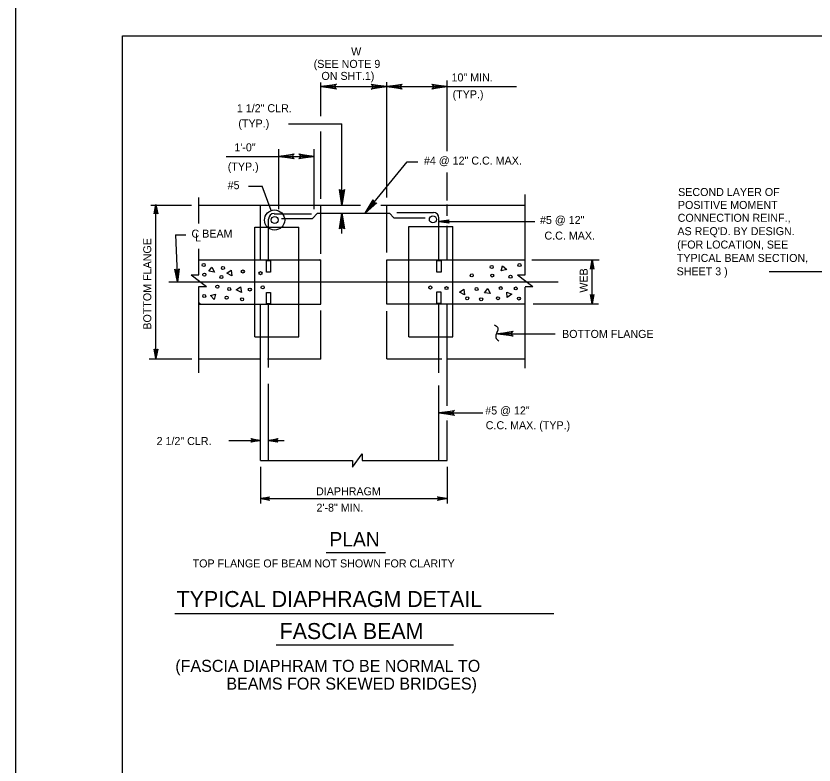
# Model space of a CAD drawing. Extents: x 639980 to 641204, y 298038 to 300414.
# Drawn here: x 639980.3 to 640279.6, y 299531.3 to 299812.3 of the extents above; entities that cross this region are included whole.
import ezdxf

# ---------------------------------------------------------------- set-up
doc = ezdxf.new("R2010")
doc.units = 0
for name, color, linetype in [('2', 7, 'Continuous'), ('3', 7, 'Continuous'), ('PLT-BNDY', 7, 'Continuous')]:
    doc.layers.add(name, color=color, linetype=linetype)

msp = doc.modelspace()

# ---------------------------------------------------------------- linework, layer by layer
at = {"layer": '2'}
for p, q in [((640020.31, 299240.78), (640020.31, 299804.78)), ((640020.31, 299804.78), (640806.31, 299804.78)), ((640142.04, 299761.53), (640142.04, 299788.07)), ((640094.66, 299774.72), (640094.66, 299787.32)), ((640094.66, 299785.77), (640094.66, 299785.77)), ((640094.66, 299785.77), (640119.35, 299785.77)), ((640109.44, 299785.77), (640109.44, 299785.77)), ((640119.35, 299744.16), (640119.35, 299787.43)), ((640119.35, 299785.77), (640142.04, 299785.77)), ((640119.35, 299785.77), (640119.35, 299785.77)), ((640142.04, 299785.77), (640168.01, 299785.77)), ((640082.53, 299771.86), (640102.51, 299771.86)), ((640102.51, 299741.38), (640102.51, 299771.86)), ((640094.66, 299743.75), (640094.66, 299769)), ((640078.85, 299739.88), (640078.85, 299762.36)), ((640092.16, 299739.88), (640092.16, 299762.36)), ((640059.1, 299759.62), (640078.85, 299759.62)), ((640078.85, 299759.62), (640092.16, 299759.62)), ((640111.27, 299738.26), (640127.05, 299757.63)), ((640127.05, 299757.63), (640130.99, 299757.63)), ((640142.04, 299743.01), (640142.04, 299753.52)), ((640067.48, 299748.48), (640072.6, 299748.48)), ((640075.98, 299739.28), (640072.6, 299748.48)), ((640048.93, 299734.45), (640048.93, 299744.14)), ((640171.3, 299715.13), (640171.3, 299745.26)), ((640030.87, 299741.38), (640046.18, 299741.38)), ((640032.79, 299683.76), (640032.79, 299741.51)), ((640048.93, 299741.38), (640071.97, 299741.38)), ((640071.97, 299720.76), (640071.97, 299741.38)), ((640071.97, 299741.38), (640109.47, 299741.38)), ((640094.66, 299723.06), (640094.66, 299741.26)), ((640117.14, 299741.38), (640142.04, 299741.38)), ((640119.35, 299723.51), (640119.35, 299741.38)), ((640142.04, 299737.33), (640142.04, 299741.63)), ((640142.04, 299741.38), (640171.3, 299741.38)), ((640077.1, 299738.13), (640091.09, 299738.13)), ((640091.49, 299736.33), (640093.41, 299738.26)), ((640093.41, 299738.26), (640120.35, 299738.26)), ((640102.51, 299730.68), (640102.51, 299738.26)), ((640122.03, 299736.58), (640120.35, 299738.26)), ((640123.12, 299738.51), (640136.91, 299738.51)), ((640074.97, 299720.76), (640074.97, 299736.13)), ((640079.82, 299736.33), (640091.49, 299736.33)), ((640122.03, 299736.58), (640133.72, 299736.58)), ((640138.91, 299721.01), (640138.91, 299736.51)), ((640138.91, 299735.21), (640174.84, 299735.21)), ((640069.91, 299691.88), (640069.91, 299733.13)), ((640069.91, 299733.13), (640086.41, 299733.13)), ((640086.41, 299691.88), (640086.41, 299733.13)), ((640127.6, 299733.38), (640144.1, 299733.38)), ((640127.6, 299691.88), (640127.6, 299733.38)), ((640142.04, 299721.01), (640142.04, 299733.61)), ((640144.1, 299691.88), (640144.1, 299733.38)), ((640040.09, 299730.19), (640040.93, 299712.51)), ((640040.09, 299730.19), (640043.95, 299730.19)), ((640048.93, 299715.13), (640048.93, 299724.97)), ((640048.93, 299720.76), (640071.97, 299720.76)), ((640071.97, 299720.76), (640094.66, 299720.76)), ((640094.66, 299704.13), (640094.66, 299720.88)), ((640119.35, 299704.13), (640119.35, 299720.76)), ((640119.35, 299720.76), (640142.04, 299720.76)), ((640142.04, 299720.76), (640171.3, 299720.76)), ((640173.8, 299720.76), (640199.05, 299720.76)), ((640196.43, 299704.26), (640196.43, 299720.76)), ((640262.77, 299716.48), (640289.71, 299716.48)), ((640046.05, 299715.13), (640048.93, 299715.13)), ((640046.05, 299715.13), (640051.8, 299710.76)), ((640168.43, 299715.13), (640171.3, 299715.13)), ((640168.43, 299715.13), (640174.18, 299710.76)), ((640037.68, 299712.51), (640183.68, 299712.51)), ((640048.93, 299678.38), (640048.93, 299710.76)), ((640048.93, 299710.76), (640051.8, 299710.76)), ((640106.94, 299712.51), (640106.94, 299712.51)), ((640171.3, 299710.76), (640174.18, 299710.76)), ((640171.3, 299680.13), (640171.3, 299710.51)), ((640119.35, 299704.26), (640142.04, 299704.26)), ((640138.91, 299678.38), (640138.91, 299704.26)), ((640142.04, 299704.26), (640171.3, 299704.26)), ((640142.04, 299666.02), (640142.04, 299704.26)), ((640174.3, 299704.26), (640198.8, 299704.26)), ((640048.93, 299704.13), (640071.97, 299704.13)), ((640071.97, 299645.51), (640071.97, 299704.13)), ((640071.97, 299704.13), (640094.66, 299704.13)), ((640074.97, 299680.41), (640074.97, 299704.13)), ((640094.66, 299683.51), (640094.66, 299701.84)), ((640119.35, 299683.63), (640119.35, 299701.62)), ((640160.89, 299693.09), (640182.49, 299693.09)), ((640069.91, 299691.88), (640086.41, 299691.88)), ((640127.6, 299691.88), (640144.1, 299691.88)), ((640030.2, 299683.63), (640046.3, 299683.63)), ((640048.93, 299683.63), (640071.97, 299683.63)), ((640074.63, 299683.63), (640094.66, 299683.63)), ((640119.35, 299683.63), (640140.04, 299683.63)), ((640142.04, 299683.63), (640171.3, 299683.63)), ((640074.97, 299645.51), (640074.97, 299674.26)), ((640138.91, 299645.51), (640138.91, 299673.63)), ((640138.91, 299663.38), (640155.41, 299663.38)), ((640142.04, 299645.51), (640142.04, 299660.6)), ((640060.1, 299653.01), (640071.97, 299653.01)), ((640074.97, 299653.01), (640080.86, 299653.01)), ((640106.44, 299643.01), (640110.07, 299648.01)), ((640110.07, 299648.01), (640110.07, 299645.51)), ((640071.97, 299645.51), (640086.79, 299645.51)), ((640081.69, 299645.51), (640106.44, 299645.51)), ((640106.44, 299645.51), (640106.44, 299643.01)), ((640110.07, 299645.51), (640133.19, 299645.51)), ((640133.41, 299645.51), (640142.04, 299645.51)), ((640071.97, 299643.13), (640071.97, 299629.38)), ((640142.04, 299643.13), (640142.04, 299629.38)), ((640071.97, 299631.26), (640142.04, 299631.26)), ((640096.67, 299611.07), (640118.83, 299611.07)), ((640039.91, 299588.23), (640182.04, 299588.23)), ((640077.91, 299576.48), (640144.41, 299576.48))]:
    msp.add_line(p, q, dxfattribs=at)
for points in [[(640100.2, 299785.07), (640099.99, 299785.47), (640094.66, 299785.77), (640100.2, 299785.07), (640100.48, 299784.83), (640094.66, 299785.77), (640099.99, 299786.03), (640100.18, 299786.43), (640094.66, 299785.77), (640100.48, 299786.69), (640100.18, 299786.43)], [(640113.81, 299786.46), (640114.02, 299786.06), (640119.35, 299785.77), (640113.81, 299786.46), (640113.53, 299786.7), (640119.35, 299785.77), (640114.03, 299785.5), (640113.83, 299785.11), (640119.35, 299785.77), (640113.53, 299784.84), (640113.83, 299785.11)], [(640124.89, 299785.07), (640124.68, 299785.47), (640119.35, 299785.77), (640124.89, 299785.07), (640125.17, 299784.83), (640119.35, 299785.77), (640124.68, 299786.03), (640124.87, 299786.43), (640119.35, 299785.77), (640125.17, 299786.69), (640124.87, 299786.43)], [(640136.5, 299786.46), (640136.71, 299786.06), (640142.04, 299785.77), (640136.5, 299786.46), (640136.22, 299786.7), (640142.04, 299785.77), (640136.71, 299785.5), (640136.52, 299785.11), (640142.04, 299785.77), (640136.22, 299784.84), (640136.52, 299785.11)], [(640084.39, 299758.92), (640084.18, 299759.33), (640078.85, 299759.62), (640084.39, 299758.92), (640084.67, 299758.68), (640078.85, 299759.62), (640084.18, 299759.88), (640084.37, 299760.28), (640078.85, 299759.62), (640084.67, 299760.54), (640084.37, 299760.28)], [(640086.63, 299760.31), (640086.83, 299759.91), (640092.16, 299759.62), (640086.63, 299760.31), (640086.34, 299760.56), (640092.16, 299759.62), (640086.84, 299759.36), (640086.64, 299758.96), (640092.16, 299759.62), (640086.34, 299758.7), (640086.64, 299758.96)], [(640103.21, 299746.92), (640102.81, 299746.71), (640102.51, 299741.38), (640103.21, 299746.92), (640103.45, 299747.2), (640102.51, 299741.38), (640102.25, 299746.71), (640101.85, 299746.9), (640102.51, 299741.38), (640101.59, 299747.2), (640101.85, 299746.9)], [(640115.3, 299742.11), (640114.86, 299742.2), (640111.27, 299738.26), (640115.3, 299742.11), (640115.67, 299742.18), (640111.27, 299738.26), (640114.43, 299742.55), (640114.24, 299742.95), (640111.27, 299738.26), (640114.23, 299743.35), (640114.24, 299742.95)], [(640032.29, 299738.26), (640032.66, 299738.38), (640032.79, 299741.51), (640032.29, 299738.26), (640032.16, 299738.13), (640032.79, 299741.51), (640033.04, 299738.38), (640033.29, 299738.26), (640032.79, 299741.51), (640033.54, 299738.13), (640033.29, 299738.26)], [(640101.82, 299732.72), (640102.22, 299732.93), (640102.51, 299738.26), (640101.82, 299732.72), (640101.57, 299732.44), (640102.51, 299738.26), (640102.78, 299732.93), (640103.17, 299732.74), (640102.51, 299738.26), (640103.44, 299732.44), (640103.17, 299732.74)], [(640142.6, 299734.75), (640142.47, 299735.02), (640138.91, 299735.21), (640142.6, 299734.75), (640142.79, 299734.59), (640138.91, 299735.21), (640142.46, 299735.39), (640142.59, 299735.65), (640138.91, 299735.21), (640142.79, 299735.83), (640142.59, 299735.65)], [(640094.66, 299720.26), (640094.04, 299720.76)], [(640195.93, 299717.51), (640196.18, 299717.63), (640196.43, 299720.76), (640195.93, 299717.51), (640195.8, 299717.26), (640196.43, 299720.76), (640196.55, 299717.63), (640196.93, 299717.51), (640196.43, 299720.76), (640197.05, 299717.26), (640196.93, 299717.51)], [(640041.29, 299717.14), (640040.96, 299716.95), (640040.93, 299712.51), (640041.29, 299717.14), (640041.48, 299717.39), (640040.93, 299712.51), (640040.5, 299716.93), (640040.16, 299717.08), (640040.93, 299712.51), (640039.93, 299717.31), (640040.16, 299717.08)], [(640196.93, 299707.51), (640196.68, 299707.51), (640196.43, 299704.26), (640196.93, 299707.51), (640197.05, 299707.76), (640196.43, 299704.26), (640196.18, 299707.38), (640195.93, 299707.51), (640196.43, 299704.26), (640195.8, 299707.76), (640195.93, 299707.51)], [(640049.43, 299704.26), (640048.93, 299704.76)], [(640166.42, 299692.4), (640166.22, 299692.8), (640160.89, 299693.09), (640166.42, 299692.4), (640166.71, 299692.15), (640160.89, 299693.09), (640166.21, 299693.35), (640166.41, 299693.75), (640160.89, 299693.09), (640166.71, 299694.02), (640166.41, 299693.75)], [(640033.29, 299687.13), (640033.04, 299687.01), (640032.79, 299683.76), (640033.29, 299687.13), (640033.54, 299687.26), (640032.79, 299683.76), (640032.66, 299687.01), (640032.41, 299687.13), (640032.79, 299683.76), (640032.16, 299687.26), (640032.41, 299687.13)], [(640144.45, 299662.69), (640144.24, 299663.09), (640138.91, 299663.38), (640144.45, 299662.69), (640144.73, 299662.44), (640138.91, 299663.38), (640144.24, 299663.64), (640144.43, 299664.04), (640138.91, 299663.38), (640144.73, 299664.31), (640144.43, 299664.04)], [(640142.04, 299661.38), (640142.04, 299661.38)], [(640068.6, 299653.51), (640068.72, 299653.26), (640071.97, 299653.01), (640068.6, 299653.51), (640068.47, 299653.76), (640071.97, 299653.01), (640068.72, 299652.88), (640068.6, 299652.63), (640071.97, 299653.01), (640068.47, 299652.38), (640068.6, 299652.63)], [(640078.35, 299652.51), (640078.22, 299652.88), (640074.97, 299653.01), (640078.35, 299652.51), (640078.47, 299652.38), (640074.97, 299653.01), (640078.22, 299653.26), (640078.35, 299653.51), (640074.97, 299653.01), (640078.47, 299653.76), (640078.35, 299653.51)], [(640142.04, 299654.13), (640142.04, 299654.13)], [(640142.04, 299646.76), (640142.04, 299646.76)], [(640075.1, 299630.76), (640074.97, 299631.01), (640071.85, 299631.26), (640075.1, 299630.76), (640075.35, 299630.51), (640071.85, 299631.26), (640074.97, 299631.38), (640075.1, 299631.63), (640071.85, 299631.26), (640075.35, 299631.88), (640075.1, 299631.63)], [(640138.66, 299631.76), (640138.79, 299631.38), (640141.91, 299631.26), (640138.66, 299631.76), (640138.41, 299631.88), (640141.91, 299631.26), (640138.79, 299631.01), (640138.66, 299630.76), (640141.91, 299631.26), (640138.41, 299630.51), (640138.66, 299630.76)]]:
    msp.add_lwpolyline(points, dxfattribs=at)
for points in [[(640074.22, 299720.55), (640075.78, 299720.55), (640075.78, 299716.22), (640074.22, 299716.22)], [(640138.14, 299720.57), (640139.7, 299720.57), (640139.7, 299716.24), (640138.14, 299716.24)], [(640052.59, 299716.54), (640053.74, 299718.08), (640054.71, 299716.25)], [(640059.34, 299715.84), (640060.95, 299716.89), (640061.24, 299714.84)], [(640162.24, 299716.73), (640162.8, 299718.58), (640164.33, 299717.19)], [(640062.93, 299709.62), (640064.55, 299710.67), (640064.83, 299708.62)], [(640053.25, 299707.5), (640055.12, 299707.93), (640054.69, 299705.91)], [(640074.2, 299708.59), (640075.76, 299708.59), (640075.76, 299704.26), (640074.2, 299704.26)], [(640138.07, 299708.82), (640139.63, 299708.82), (640139.63, 299704.48), (640138.07, 299704.48)], [(640146.61, 299708.72), (640148.23, 299709.77), (640148.51, 299707.72)], [(640156.05, 299708.49), (640157.2, 299710.02), (640158.17, 299708.2)], [(640164.44, 299706.74), (640164.34, 299708.66), (640166.25, 299707.88)]]:
    msp.add_lwpolyline(points, close=True, dxfattribs=at)
for centre, radius in [((640077.29, 299735.74), 3.78), ((640136.65, 299735.98), 1.32), ((640077.34, 299735.75), 1.32), ((640050.72, 299718.88), 0.571), ((640169.13, 299718.88), 0.571), ((640057.94, 299717.75), 0.571), ((640065.38, 299716.44), 0.571), ((640072.01, 299715.81), 0.571), ((640158.71, 299718.11), 0.571), ((640050.95, 299715.27), 0.571), ((640057.35, 299714.37), 0.571), ((640151.22, 299715), 0.571), ((640158.89, 299714.91), 0.571), ((640165.75, 299714.5), 0.571), ((640055.82, 299710.76), 0.571), ((640060.28, 299709.86), 0.571), ((640068, 299709.67), 0.571), ((640072.82, 299710.49), 0.571), ((640135.71, 299710.44), 0.571), ((640141.75, 299710.22), 0.571), ((640153.03, 299709.86), 0.571), ((640162.09, 299710.22), 0.571), ((640167.73, 299710.08), 0.571), ((640050.9, 299707.24), 0.571), ((640059.29, 299706.61), 0.571), ((640065.11, 299706.02), 0.571), ((640149.51, 299706.38), 0.571), ((640154.74, 299706.02), 0.571), ((640161.06, 299706.43), 0.571), ((640168.9, 299706.29), 0.571)]:
    msp.add_circle(centre, radius, dxfattribs=at)
for centre, start, end in [((640077.09, 299736.11), 90, 180), ((640136.87, 299736.49), 0, 90)]:
    msp.add_arc(centre, 2.06, start, end, dxfattribs=at)
msp.add_spline([(640159.66, 299696.48), (640161.01, 299695.24), (640160.22, 299691.75), (640161.35, 299690.39)], degree=3, dxfattribs=at)
at = {"layer": 'PLT-BNDY'}
msp.add_lwpolyline([(639980.31, 299819.78), (640821.31, 299819.78), (640821.31, 299225.78), (639980.31, 299225.78)], close=True, dxfattribs=at)

# ---------------------------------------------------------------- texts
at = {"layer": '2'}
for s, height, p in [('W', 3, (640106, 299797.47)), ('(SEE NOTE 9', 3, (640091.95, 299792.8)), ('ON SHT.1)', 3, (640094.86, 299788.3)), ('10" MIN.', 3, (640143.63, 299787.72)), ('(TYP.)', 3, (640144.04, 299781.39)), ('1 1/2" CLR.', 3, (640063.13, 299776.19)), ('(TYP.)', 3, (640063.7, 299770.46)), ('1\'-0"', 3, (640062.2, 299761.51)), ('#4 @ 12" C.C. MAX.', 3, (640133.29, 299756.53)), ('(TYP.)', 3, (640059.73, 299754.29)), ('#5', 3, (640059.68, 299747.32)), ('#5 @ 12"', 3, (640176.81, 299734.27)), ('C BEAM', 3, (640046.12, 299729.14)), ('C.C. MAX.', 3, (640178.48, 299728.41)), ('L', 3, (640047.44, 299727.71)), ('BOTTOM FLANGE', 3, (640185.08, 299691.53)), ('#5 @ 12"', 3, (640156.27, 299662.82)), ('C.C. MAX. (TYP.)', 3, (640156.47, 299657.29)), ('2 1/2" CLR.', 3, (640033.04, 299651.36)), ('DIAPHRAGM', 3, (640092.82, 299632.51)), ('2\'-8" MIN.', 3, (640092.99, 299626.38)), ('PLAN', 5.4, (640097.85, 299613.31)), ('TOP FLANGE OF BEAM NOT SHOWN FOR CLARITY', 3, (640046.54, 299605.46)), ('TYPICAL DIAPHRAGM DETAIL', 6, (640040.54, 299590.6)), ('FASCIA BEAM', 6, (640079.16, 299578.6)), ('(FASCIA DIAPHRAM TO BE NORMAL TO ', 4.5, (640040.06, 299566.3)), ('BEAMS FOR SKEWED BRIDGES)', 4.5, (640059.21, 299559.64))]:
    msp.add_text(s, height=height, dxfattribs=at).set_placement(p)
for s, p in [('BOTTOM FLANGE', (640031.04, 299694.63)), ('WEB', (640194.68, 299708.51))]:
    msp.add_text(s, height=3, rotation=90, dxfattribs=at).set_placement(p)
at = {"layer": '3'}
for s, height, p in [('SECOND LAYER OF', 2.9968, (640228.61, 299744.75)), ('POSITIVE MOMENT', 2.9968, (640228.53, 299739.91)), ('CONNECTION REINF.,', 2.9968, (640228.44, 299735.08)), ("AS REQ'D. BY DESIGN.", 2.9968, (640228.34, 299730.07)), ('(FOR LOCATION, SEE', 2.9968, (640228.24, 299725.05)), ('TYPICAL BEAM SECTION,', 2.9968, (640228.14, 299720.03)), ('SHEET 3 )', 2.997, (640228.04, 299715.01))]:
    msp.add_text(s, height=height, dxfattribs=at).set_placement(p)

doc.saveas('drawing.dxf')
